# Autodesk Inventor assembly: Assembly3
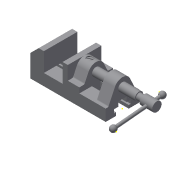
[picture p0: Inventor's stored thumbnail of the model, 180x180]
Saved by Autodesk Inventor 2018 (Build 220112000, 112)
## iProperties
Created: 2016-05
Part Number: Assembly3
Document SubType Name: Assembly
Designer: Sandeep
Author: Sandeep
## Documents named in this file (11)
- E:\_Deepak\Inventor\Autodesk Inventor_2018_Project\Resources\Inventor_2018_tut\c09_Inv_tut_2018\c09_tut04_inv\Bench vice assembly.iam
- E:\_Deepak\Inventor\Autodesk Inventor_2018_Project\Resources\Inventor_2018_tut\c09_Inv_tut_2018\c09_tut04_inv\Base1.ipt
- E:\_Deepak\Inventor\Autodesk Inventor_2018_Project\Resources\Inventor_2018_tut\c09_Inv_tut_2018\c09_tut04_inv\base plate.ipt
- E:\_Deepak\Inventor\Autodesk Inventor_2018_Project\Resources\Inventor_2018_tut\c09_Inv_tut_2018\c09_tut04_inv\vice jaw.ipt
- E:\_Deepak\Inventor\Autodesk Inventor_2018_Project\Resources\Inventor_2018_tut\c09_Inv_tut_2018\c09_tut04_inv\jaw screw.ipt
- E:\_Deepak\Inventor\Autodesk Inventor_2018_Project\Resources\Inventor_2018_tut\c09_Inv_tut_2018\c09_tut04_inv\clamping plate.ipt
- E:\_Deepak\Inventor\Autodesk Inventor_2018_Project\Resources\Inventor_2018_tut\c09_Inv_tut_2018\c09_tut04_inv\Screw Bar.ipt
- E:\_Deepak\Inventor\Autodesk Inventor_2018_Project\Resources\Inventor_2018_tut\c09_Inv_tut_2018\c09_tut04_inv\bar globes.ipt
- E:\_Deepak\Inventor\Autodesk Inventor_2018_Project\Resources\Inventor_2018_tut\c09_Inv_tut_2018\c09_tut04_inv\set scew 1.ipt
- E:\_Deepak\Inventor\Autodesk Inventor_2018_Project\Resources\Inventor_2018_tut\c09_Inv_tut_2018\c09_tut04_inv\set scew 2.ipt
- E:\_Deepak\Inventor\Autodesk Inventor_2018_Project\Resources\Inventor_2018_tut\c09_Inv_tut_2018\c09_tut04_inv\Oval Filister.ipt
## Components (16 placed, 10 different names)
1. Base1:1 — Slider:1, Cylindrical:1, Insert:10, Mate:15, Mate:16, Mate:17, Mate:18, Mate:19, Mate:21, Mate:23
2. base plate:1 — Insert:10, Mate:15, Mate:20, Mate:22
3. base plate:2 — Mate:16, Mate:17, Mate:18, Mate:24, Mate:25, Mate:26
4. vice jaw:1 — Slider:1, Mate:1, Insert:9, Mate:2, Mate:12, Mate:13, Mate:14
5. jaw screw:1 — Cylindrical:1, Mate:1, Cylindrical:2
6. clamping plate:1 — Insert:9, Mate:2, Mate:27, Mate:28, Mate:29, Mate:30
7. Screw Bar:1 — Cylindrical:2, Rigid:2, Rigid:3
8. bar globes:1 — Rigid:2
9. bar globes:2 — Rigid:3
10. Oval Filister:1 — Mate:12, Mate:13, Mate:14
11. set scew 1:1 — Mate:19, Mate:20
12. set scew 1:2 — Mate:21, Mate:22
13. set scew 1:3 — Mate:23, Mate:24
14. set scew 1:4 — Mate:25, Mate:26
15. set scew 2:1 — Mate:27, Mate:28
16. set scew 2:2 — Mate:29, Mate:30
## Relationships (28: Mate 21, CylindricalJoint 2, WeldJoint 2, Insert 2, TranslationJoint 1)
- Slider:1 [TranslationJoint]: Base1:1 ↔ vice jaw:1
- Cylindrical:1: Base1:1 ↔ jaw screw:1
- Mate:1: vice jaw:1 ↔ jaw screw:1
- Cylindrical:2: jaw screw:1 ↔ Screw Bar:1
- Rigid:2 [WeldJoint]: Screw Bar:1 ↔ bar globes:1
- Rigid:3 [WeldJoint]: Screw Bar:1 ↔ bar globes:2
- Insert:9: vice jaw:1 ↔ clamping plate:1
- Mate:2: vice jaw:1 ↔ clamping plate:1
- Mate:12: vice jaw:1 ↔ Oval Filister:1
- Mate:13: vice jaw:1 ↔ Oval Filister:1
- Mate:14: vice jaw:1 ↔ Oval Filister:1
- Insert:10: Base1:1 ↔ base plate:1
- Mate:15: Base1:1 ↔ base plate:1
- Mate:16: Base1:1 ↔ base plate:2
- Mate:17: Base1:1 ↔ base plate:2
- Mate:18: Base1:1 ↔ base plate:2
- Mate:19: Base1:1 ↔ set scew 1:1
- Mate:20: base plate:1 ↔ set scew 1:1
- Mate:21: Base1:1 ↔ set scew 1:2
- Mate:22: base plate:1 ↔ set scew 1:2
- Mate:23: Base1:1 ↔ set scew 1:3
- Mate:24: base plate:2 ↔ set scew 1:3
- Mate:25: base plate:2 ↔ set scew 1:4
- Mate:26: base plate:2 ↔ set scew 1:4
- Mate:27: clamping plate:1 ↔ set scew 2:1
- Mate:28: clamping plate:1 ↔ set scew 2:1
- Mate:29: clamping plate:1 ↔ set scew 2:2
- Mate:30: clamping plate:1 ↔ set scew 2:2
